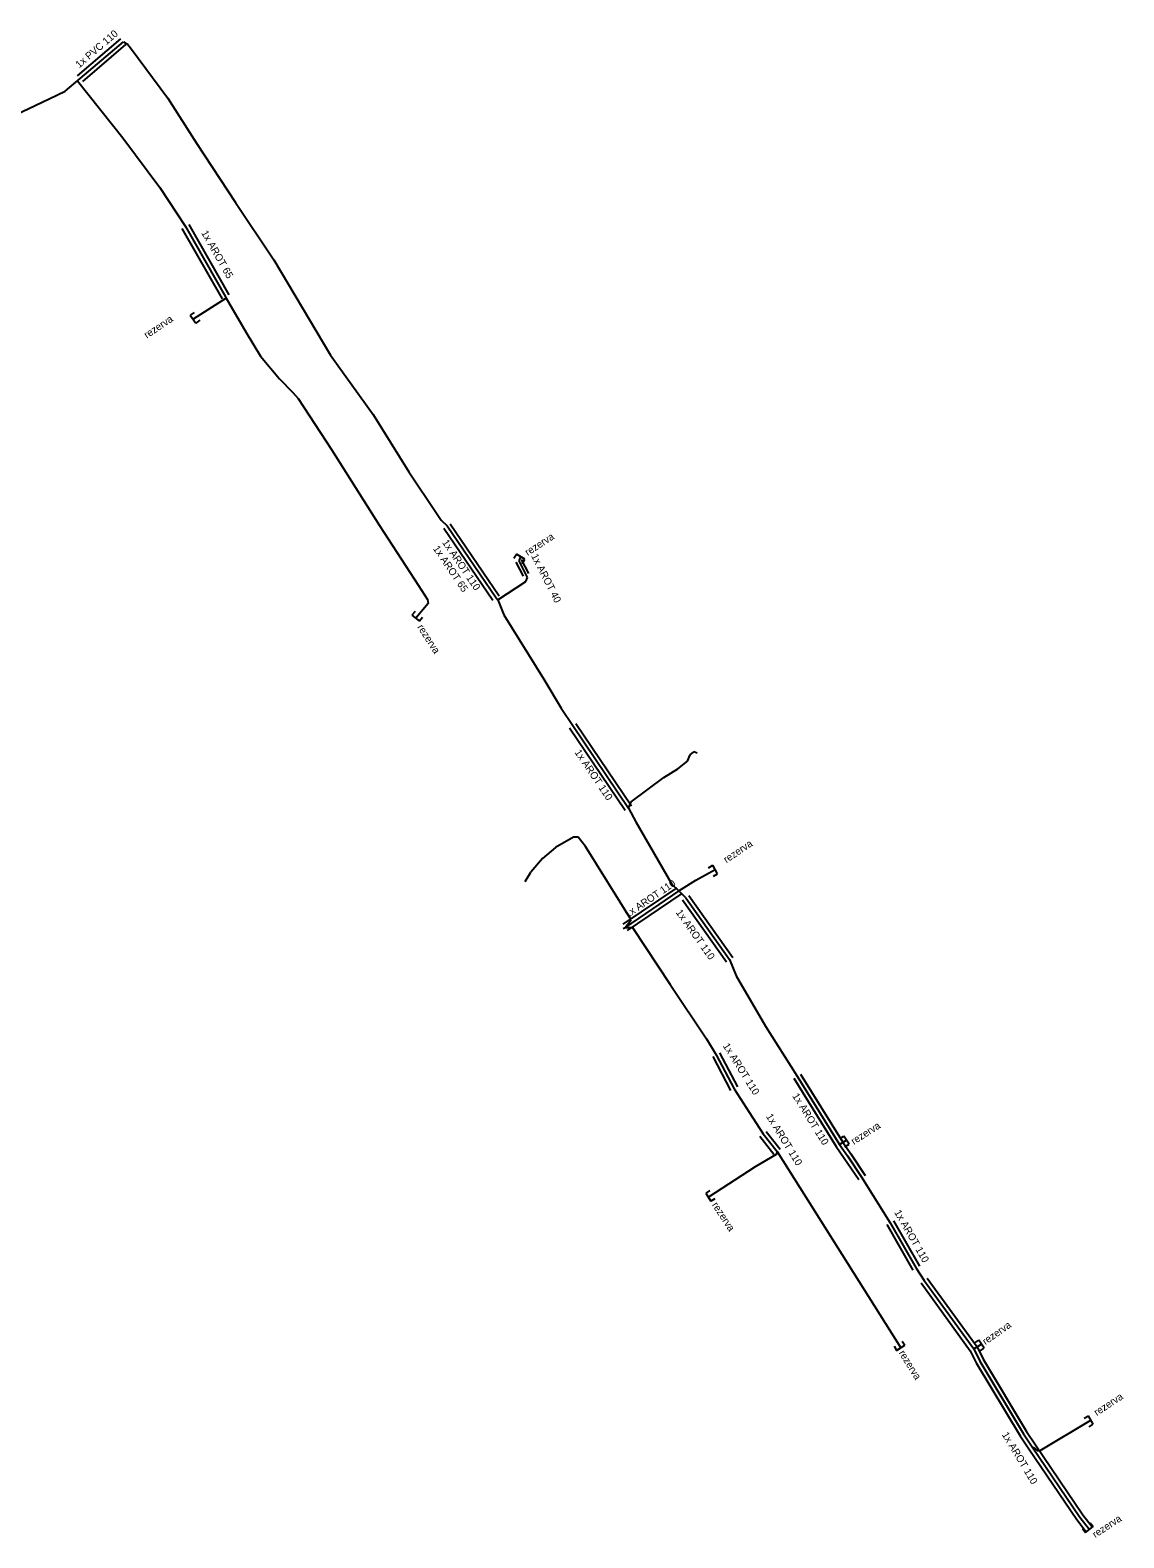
# Model space of a CAD drawing. Extents: x -651943 to -618711, y -1138561 to -1100552.
# Drawn here: x -650967 to -650854.2, y -1113417 to -1113261.5 of the extents above; entities that cross this region are included whole.
import ezdxf

# ---------------------------------------------------------------- set-up
doc = ezdxf.new("R2010")
doc.units = 0
doc.layers.add('KT trasa', color=7, linetype='Continuous')
doc.layers.add('KT zařízení', color=7, linetype='Continuous')

# ---------------------------------------------------------------- blocks, each defined once
blk = doc.blocks.new('TVREZ')
at = {"layer": 'KT zařízení'}
for p, q in [((-0.05, 0.05), (0, 0.05)), ((0, -0.05), (0, 0.05)), ((-0.05, -0.05), (0, -0.05))]:
    blk.add_line(p, q, dxfattribs=at)

msp = doc.modelspace()

# ---------------------------------------------------------------- linework, layer by layer
at = {"layer": 'KT trasa'}
for p, q in [((-650961.83, -1113266.47), (-650957.38, -1113262.67)), ((-650957.38, -1113262.67), (-650956.92, -1113262.94)), ((-650956.92, -1113262.94), (-650956.65, -1113263.31)), ((-650956.65, -1113263.31), (-650952.81, -1113268.49)), ((-650963.4, -1113267.77), (-650961.83, -1113266.47)), ((-650962.11, -1113266.7), (-650957.44, -1113272.58)), ((-650969.23, -1113270.55), (-650965.03, -1113268.55)), ((-650965.03, -1113268.55), (-650963.4, -1113267.77)), ((-650952.81, -1113268.49), (-650949.84, -1113273.14)), ((-650957.44, -1113272.58), (-650953.63, -1113277.72)), ((-650949.84, -1113273.14), (-650945.82, -1113279.27)), ((-650953.63, -1113277.72), (-650950.98, -1113281.73)), ((-650945.82, -1113279.27), (-650941.88, -1113285.16)), ((-650950.98, -1113281.73), (-650946.85, -1113288.98)), ((-650941.88, -1113285.16), (-650936.01, -1113294.99)), ((-650946.85, -1113288.98), (-650946.78, -1113289.13)), ((-650946.78, -1113289.13), (-650950.18, -1113291.29)), ((-650946.78, -1113289.13), (-650944.71, -1113292.66)), ((-650944.71, -1113292.66), (-650943.24, -1113295.11)), ((-650943.24, -1113295.11), (-650941.29, -1113297.45)), ((-650936.01, -1113294.99), (-650931.62, -1113301.13)), ((-650941.29, -1113297.45), (-650939.9, -1113298.87)), ((-650939.9, -1113298.87), (-650939.37, -1113299.46)), ((-650939.37, -1113299.46), (-650935.91, -1113304.74)), ((-650931.62, -1113301.13), (-650927.95, -1113307.04)), ((-650935.91, -1113304.74), (-650930.96, -1113312.58)), ((-650927.95, -1113307.04), (-650925.1, -1113311.31)), ((-650925.1, -1113311.31), (-650924.62, -1113312.02)), ((-650924.62, -1113312.02), (-650923.99, -1113312.63)), ((-650930.96, -1113312.58), (-650926.95, -1113318.78)), ((-650923.99, -1113312.63), (-650918.95, -1113320.05)), ((-650916.58, -1113316.22), (-650916.41, -1113315.8)), ((-650915.84, -1113317.68), (-650916.58, -1113316.22)), ((-650918.78, -1113320.26), (-650915.89, -1113318.34)), ((-650915.89, -1113318.34), (-650915.72, -1113317.94)), ((-650915.72, -1113317.94), (-650915.84, -1113317.68)), ((-650926.95, -1113318.78), (-650926.01, -1113320.22)), ((-650918.95, -1113320.05), (-650918.78, -1113320.26)), ((-650925.96, -1113320.61), (-650927.22, -1113322.14)), ((-650926.01, -1113320.22), (-650925.96, -1113320.61)), ((-650918.78, -1113320.26), (-650918.16, -1113321.81)), ((-650918.16, -1113321.81), (-650914.02, -1113328.42)), ((-650914.02, -1113328.42), (-650912.24, -1113331.43)), ((-650912.24, -1113331.43), (-650911.03, -1113333.23)), ((-650911.03, -1113333.23), (-650905.29, -1113341.73)), ((-650900.21, -1113337.67), (-650899.22, -1113336.89)), ((-650899.22, -1113336.89), (-650898.93, -1113336.24)), ((-650898.93, -1113336.24), (-650898.55, -1113335.93)), ((-650898.21, -1113336.06), (-650898.55, -1113335.93)), ((-650905.03, -1113341.1), (-650901.63, -1113338.58)), ((-650901.63, -1113338.58), (-650900.21, -1113337.67)), ((-650905.29, -1113341.73), (-650905.03, -1113341.1)), ((-650905.29, -1113341.73), (-650904.52, -1113343.15)), ((-650904.52, -1113343.15), (-650900.83, -1113349.58)), ((-650910.96, -1113344.74), (-650912.82, -1113345.81)), ((-650910.49, -1113344.75), (-650910.96, -1113344.74)), ((-650909.73, -1113345.69), (-650910.49, -1113344.75)), ((-650912.82, -1113345.81), (-650914.16, -1113346.93)), ((-650905.01, -1113353.26), (-650909.73, -1113345.69)), ((-650914.16, -1113346.93), (-650915.37, -1113348.35)), ((-650898.33, -1113349.18), (-650896.34, -1113348.07)), ((-650915.94, -1113349.31), (-650915.37, -1113348.35)), ((-650900.83, -1113349.58), (-650900.09, -1113350.28)), ((-650900.09, -1113350.28), (-650898.33, -1113349.18)), ((-650900.09, -1113350.28), (-650905.64, -1113354.05)), ((-650899.39, -1113350.98), (-650900.09, -1113350.28)), ((-650899.39, -1113350.98), (-650894.86, -1113357.37)), ((-650905.83, -1113354.17), (-650905.64, -1113354.05)), ((-650905.64, -1113354.05), (-650905.01, -1113353.26)), ((-650905.64, -1113354.05), (-650904.89, -1113354.04)), ((-650904.89, -1113354.04), (-650900.99, -1113359.92)), ((-650894.86, -1113357.37), (-650894.2, -1113359.03)), ((-650894.2, -1113359.03), (-650891.15, -1113364.22)), ((-650900.99, -1113359.92), (-650897.26, -1113365.53)), ((-650891.15, -1113364.22), (-650887.89, -1113369.4)), ((-650897.26, -1113365.53), (-650896.25, -1113367.19)), ((-650896.25, -1113367.19), (-650894.4, -1113370.69)), ((-650887.89, -1113369.4), (-650883.52, -1113376.43)), ((-650894.4, -1113370.69), (-650892.85, -1113373.11)), ((-650892.85, -1113373.11), (-650891.41, -1113375.34)), ((-650891.41, -1113375.34), (-650889.97, -1113377.18)), ((-650883.52, -1113376.43), (-650882.81, -1113375.99)), ((-650890.07, -1113377.49), (-650892.23, -1113378.76)), ((-650889.97, -1113377.18), (-650890.07, -1113377.49)), ((-650889.97, -1113377.18), (-650884.87, -1113385.23)), ((-650883.52, -1113376.43), (-650882.69, -1113377.62)), ((-650882.69, -1113377.62), (-650881.21, -1113379.85)), ((-650892.23, -1113378.76), (-650897.05, -1113381.88)), ((-650881.21, -1113379.85), (-650880.44, -1113381.12)), ((-650880.44, -1113381.12), (-650878.3, -1113384.51)), ((-650884.87, -1113385.23), (-650877.21, -1113397.42)), ((-650878.3, -1113384.51), (-650875.62, -1113389.2)), ((-650875.62, -1113389.2), (-650874.79, -1113390.48)), ((-650874.79, -1113390.48), (-650869.68, -1113397.53)), ((-650869.68, -1113397.53), (-650868.88, -1113397.03)), ((-650869.68, -1113397.53), (-650869.05, -1113398.78)), ((-650869.05, -1113398.78), (-650864.55, -1113406.28)), ((-650862.84, -1113408.03), (-650857.6, -1113404.87)), ((-650864.55, -1113406.28), (-650863.66, -1113407.63)), ((-650863.66, -1113407.63), (-650863.37, -1113407.76)), ((-650863.66, -1113407.63), (-650858.73, -1113414.89)), ((-650863.37, -1113407.76), (-650863.15, -1113408.02)), ((-650863.15, -1113408.02), (-650862.84, -1113408.03)), ((-650858.73, -1113414.89), (-650857.75, -1113416.16))]:
    msp.add_line(p, q, dxfattribs=at)
at = {"layer": 'KT zařízení'}
for p, q in [((-650962.1, -1113266.17), (-650957.65, -1113262.36)), ((-650961.58, -1113266.77), (-650957.13, -1113262.97)), ((-650951.34, -1113281.93), (-650947.21, -1113289.18)), ((-650950.64, -1113281.53), (-650946.51, -1113288.78)), ((-650924.33, -1113312.85), (-650919.29, -1113320.27)), ((-650923.67, -1113312.41), (-650918.63, -1113319.82)), ((-650916.12, -1113317.81), (-650916.86, -1113316.35)), ((-650915.58, -1113317.54), (-650916.32, -1113316.08)), ((-650911.37, -1113333.45), (-650905.63, -1113341.95)), ((-650910.71, -1113333.01), (-650904.97, -1113341.51)), ((-650900.32, -1113349.95), (-650905.87, -1113353.72)), ((-650899.88, -1113350.61), (-650905.43, -1113354.38)), ((-650899.73, -1113351.21), (-650895.2, -1113357.6)), ((-650899.07, -1113350.75), (-650894.54, -1113357.14)), ((-650896.61, -1113367.38), (-650894.76, -1113370.88)), ((-650895.91, -1113367), (-650894.06, -1113370.5)), ((-650888.24, -1113369.61), (-650883.86, -1113376.65)), ((-650887.56, -1113369.19), (-650883.2, -1113376.21)), ((-650891.73, -1113375.59), (-650890.3, -1113377.43)), ((-650891.1, -1113375.09), (-650889.66, -1113376.93)), ((-650883.86, -1113376.65), (-650883.04, -1113377.84)), ((-650883.2, -1113376.21), (-650882.36, -1113377.4)), ((-650882.36, -1113377.4), (-650880.89, -1113379.63)), ((-650883.04, -1113377.84), (-650881.55, -1113380.07)), ((-650878.66, -1113384.71), (-650875.98, -1113389.4)), ((-650877.96, -1113384.31), (-650875.28, -1113389)), ((-650875.12, -1113390.71), (-650870.04, -1113397.73)), ((-650874.48, -1113390.25), (-650869.34, -1113397.33)), ((-650870.04, -1113397.73), (-650869.42, -1113398.96)), ((-650869.34, -1113397.33), (-650868.7, -1113398.6)), ((-650869.42, -1113398.96), (-650864.89, -1113406.5)), ((-650868.7, -1113398.6), (-650864.23, -1113406.06)), ((-650864.89, -1113406.5), (-650864.01, -1113407.84)), ((-650864.23, -1113406.06), (-650863.33, -1113407.42)), ((-650864.01, -1113407.84), (-650859.06, -1113415.13)), ((-650863.33, -1113407.42), (-650858.42, -1113414.65)), ((-650858.42, -1113414.65), (-650857.44, -1113415.92)), ((-650859.06, -1113415.13), (-650858.08, -1113416.4))]:
    msp.add_line(p, q, dxfattribs=at)

# ---------------------------------------------------------------- block references
for p, xscale, yscale, rotation in [((-650950.19, -1113291.29), 10.000019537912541, 10.000019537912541, -144.4104955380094), ((-650916.42, -1113315.8), 9.999996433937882, 9.999996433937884, 58.54613803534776), ((-650927.23, -1113322.14), 10.000011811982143, 10.000011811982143, -128.9065243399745), ((-650896.35, -1113348.07), 10.000010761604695, 10.000010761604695, 29.90296683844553), ((-650882.82, -1113375.99), 10.000017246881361, 10.000017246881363, 32.75431885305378), ((-650897.06, -1113381.88), 10.000001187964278, 10.00000118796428, -148.3106612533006), ((-650877.22, -1113397.42), 10.000021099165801, 10.0000210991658, -57.898432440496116), ((-650868.89, -1113397.03), 9.999994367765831, 9.999994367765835, 34.70922663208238), ((-650857.61, -1113404.87), 10.000001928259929, 10.000001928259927, 30.538444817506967), ((-650857.76, -1113416.16), 10.000005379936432, 10.000005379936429, -52.49205270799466)]:
    msp.add_blockref('TVREZ', p, dxfattribs=dict(at, xscale=xscale, yscale=yscale, rotation=rotation))

# ---------------------------------------------------------------- texts
for s, rotation, p in [('1x PVC 110', 40.4951, (-650961.94, -1113265.43)), ('1x AROT 65', 299.6682, (-650949.38, -1113282.39)), ('rezerva', 33.8101, (-650954.96, -1113293.31)), ('rezerva', 32.9466, (-650915.68, -1113315.73)), ('1x AROT 65', 304.1861, (-650925.49, -1113314.97)), ('1x AROT 110', 304.1861, (-650924.54, -1113314.33)), ('1x AROT 40', 296.8781, (-650915.35, -1113315.72)), ('rezerva', 302.6085, (-650927.1, -1113323.07)), ('1x AROT 110', 304.0309, (-650910.88, -1113335.99)), ('rezerva', 33.9601, (-650895.19, -1113347.44)), ('1x AROT 110', 34.1875, (-650905.37, -1113353.09)), ('1x AROT 110', 305.3336, (-650900.45, -1113352.51)), ('1x AROT 110', 302.0875, (-650895.59, -1113366.27)), ('1x AROT 110', 301.865, (-650888.43, -1113371.43)), ('1x AROT 110', 301.7056, (-650891.14, -1113373.54)), ('rezerva', 32.6797, (-650882.05, -1113376.49)), ('rezerva', 303.104, (-650896.72, -1113382.68)), ('1x AROT 110', 299.7449, (-650877.91, -1113383.44)), ('rezerva', 35.0322, (-650868.48, -1113397.15)), ('rezerva', 301.7125, (-650877.45, -1113397.95)), ('rezerva', 33.5038, (-650856.99, -1113404.47)), ('1x AROT 110', 300.9638, (-650866.81, -1113406.37)), ('rezerva', 33.5038, (-650857.15, -1113417.06))]:
    msp.add_text(s, height=0.75, rotation=rotation, dxfattribs=at).set_placement(p)

doc.saveas('drawing.dxf')
